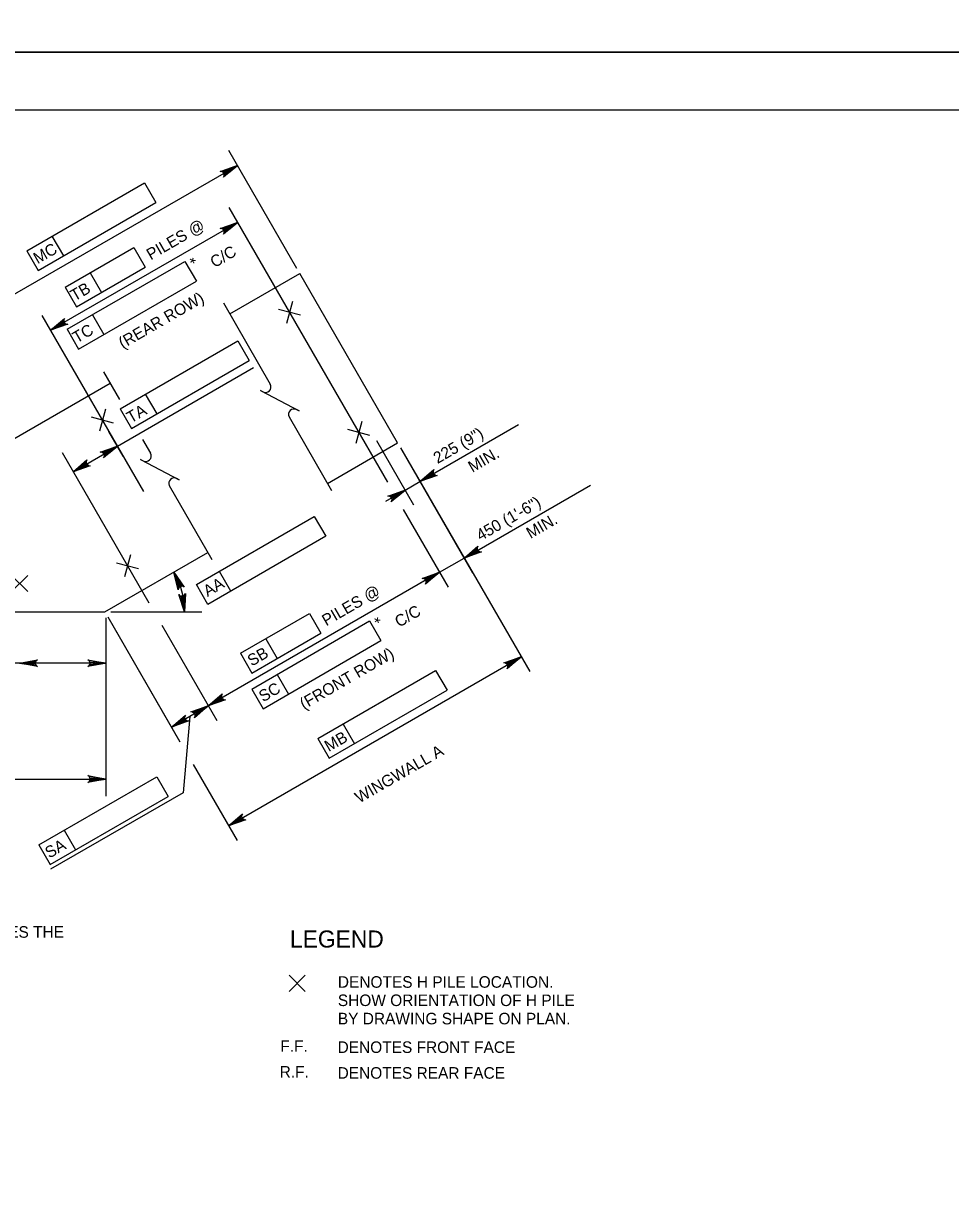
# Model space of a CAD drawing. Extents: x 638340 to 640241, y 295465 to 298435.
# Drawn here: x 639661.4 to 639902.2, y 295766.2 to 296067 of the extents above; entities that cross this region are included whole.
import ezdxf

# ---------------------------------------------------------------- set-up
doc = ezdxf.new("R2010")
doc.units = 0
for name, color, linetype in [('2', 7, 'Continuous'), ('3', 7, 'Continuous'), ('4', 7, 'Continuous'), ('PLT-BNDY', 7, 'Continuous')]:
    doc.layers.add(name, color=color, linetype=linetype)

# ---------------------------------------------------------------- blocks, each defined once
blk = doc.blocks.new('PILE')
at = {"layer": '2'}
for p, q in [((-2.651625, -2.651625), (2.651625, 2.651625)), ((-2.651625, 2.651625), (2.651625, -2.651625))]:
    blk.add_line(p, q, dxfattribs=at)

msp = doc.modelspace()

# ---------------------------------------------------------------- linework, layer by layer
at = {"layer": '2'}
for p, q in [((639316.46, 296044.46), (640102.46, 296044.46)), ((639732.41, 296003.31), (639714.76, 296033.89)), ((639642.12, 295986.84), (639716.97, 296030.05)), ((639662.28, 296007.88), (639692.86, 296025.53)), ((639692.86, 296025.53), (639695.81, 296020.41)), ((639665.24, 296002.76), (639695.81, 296020.41)), ((639714.78, 296019.09), (639755.91, 295947.84)), ((639716.99, 296015.26), (639668.49, 295987.25)), ((639668.83, 296011.66), (639671.79, 296006.54)), ((639662.28, 296007.88), (639665.24, 296002.76)), ((639672.23, 295998.41), (639690.11, 296008.73)), ((639690.11, 296008.73), (639693.07, 296003.61)), ((639672.79, 295987.49), (639703.37, 296005.13)), ((639703.37, 296005.13), (639706.32, 296000.02)), ((639675.19, 295993.29), (639693.07, 296003.61)), ((639678.78, 296002.19), (639681.73, 295997.07)), ((639672.23, 295998.41), (639675.19, 295993.29)), ((639675.74, 295982.38), (639706.32, 296000.02)), ((639692.67, 295945.37), (639666.27, 295991.09)), ((639679.34, 295991.27), (639682.29, 295986.16)), ((639672.79, 295987.49), (639675.74, 295982.38)), ((639686.52, 295966.88), (639717.1, 295984.52)), ((639717.1, 295984.52), (639720.05, 295979.4)), ((639685.85, 295957.18), (639721.13, 295977.54)), ((639689.47, 295961.76), (639720.05, 295979.4)), ((639693.07, 295970.66), (639696.02, 295965.54)), ((639686.52, 295966.88), (639689.47, 295961.76)), ((639764.35, 295947.99), (639789.98, 295962.79)), ((639687.35, 295954.58), (639683.64, 295961.01)), ((639674.32, 295950.52), (639685.85, 295957.18)), ((639753.09, 295958.63), (639762.73, 295941.94)), ((639759.33, 295956.69), (639766.57, 295944.15)), ((639759.33, 295956.69), (639778.04, 295924.28)), ((639759.33, 295956.69), (639792.85, 295898.63)), ((639671.45, 295955.5), (639693.97, 295916.48)), ((639760.51, 295945.77), (639764.35, 295947.99)), ((639775.83, 295928.11), (639808.67, 295947.08)), ((639760.51, 295945.77), (639755.4, 295942.82)), ((639706.37, 295921.21), (639736.93, 295938.89)), ((639736.93, 295938.89), (639739.89, 295933.78)), ((639760.01, 295940.74), (639771.65, 295920.59)), ((639739.89, 295933.78), (639709.33, 295916.1)), ((639769.43, 295924.42), (639775.83, 295928.11)), ((639769.43, 295924.42), (639709.4, 295889.76)), ((639715.25, 295919.53), (639712.3, 295924.64)), ((639709.33, 295916.1), (639706.37, 295921.21)), ((639766.88, 295922.95), (639764.32, 295921.47)), ((639684.13, 295914.16), (639707.7, 295914.16)), ((639682.78, 295912.62), (639682.78, 295866.33)), ((639683.36, 295912.83), (639702.07, 295880.42)), ((639683.36, 295912.83), (639701.95, 295880.63)), ((639717.79, 295903.39), (639735.65, 295913.74)), ((639720.73, 295894.1), (639751.28, 295911.79)), ((639735.65, 295913.74), (639738.62, 295908.63)), ((639751.28, 295911.79), (639754.25, 295906.68)), ((639697.33, 295910.68), (639711.61, 295885.93)), ((639720.75, 295898.28), (639738.62, 295908.63)), ((639723.69, 295888.99), (639754.25, 295906.68)), ((639724.33, 295907.18), (639727.3, 295902.07)), ((639714.66, 295858.61), (639790.63, 295902.47)), ((639717.79, 295903.39), (639720.75, 295898.28)), ((639682.78, 295900.81), (639619.52, 295900.81)), ((639737.86, 295881.25), (639768.43, 295898.91)), ((639768.43, 295898.91), (639771.39, 295893.79)), ((639727.28, 295897.89), (639730.24, 295892.78)), ((639720.73, 295894.1), (639723.69, 295888.99)), ((639740.81, 295876.14), (639771.39, 295893.79)), ((639709.4, 295889.76), (639699.86, 295884.25)), ((639704.67, 295887.03), (639702.86, 295867.18)), ((639744.41, 295885.04), (639747.36, 295879.92)), ((639737.86, 295881.25), (639740.81, 295876.14)), ((639705.49, 295874.49), (639716.88, 295854.77)), ((639523.08, 295870.76), (639682.78, 295870.76)), ((639665.46, 295853.68), (639696.04, 295871.31)), ((639696.04, 295871.31), (639698.99, 295866.2)), ((639668.41, 295848.56), (639698.99, 295866.2)), ((639702.86, 295867.18), (639668.49, 295847.34)), ((639672.01, 295857.46), (639674.96, 295852.34)), ((639665.46, 295853.68), (639668.41, 295848.56))]:
    msp.add_line(p, q, dxfattribs=at)
for points in [[(639716.97, 296030.05), (639713.37, 296026.97), (639713.56, 296027.36), (639713.56, 296027.72), (639713.45, 296028.02), (639713.25, 296028.27), (639712.93, 296028.44), (639712.5, 296028.48), (639716.97, 296030.05), (639712.93, 296028.44), (639713.25, 296028.27), (639716.97, 296030.05), (639713.45, 296028.02), (639713.56, 296027.72), (639716.97, 296030.05), (639713.56, 296027.36)], [(639716.99, 296015.26), (639713.39, 296012.17), (639713.58, 296012.56), (639713.58, 296012.93), (639713.47, 296013.23), (639713.27, 296013.47), (639712.95, 296013.65), (639712.52, 296013.68), (639716.99, 296015.26), (639712.95, 296013.65), (639713.27, 296013.47), (639716.99, 296015.26), (639713.47, 296013.23), (639713.58, 296012.93), (639716.99, 296015.26), (639713.58, 296012.56)], [(639668.49, 295987.25), (639672.09, 295990.34), (639671.9, 295989.95), (639671.89, 295989.58), (639672, 295989.28), (639672.21, 295989.04), (639672.52, 295988.86), (639672.96, 295988.83), (639668.49, 295987.25), (639672.52, 295988.86), (639672.21, 295989.04), (639668.49, 295987.25), (639672, 295989.28), (639671.89, 295989.58), (639668.49, 295987.25), (639671.9, 295989.95)], [(639685.85, 295957.18), (639682.25, 295954.09), (639682.44, 295954.49), (639682.44, 295954.85), (639682.33, 295955.15), (639682.13, 295955.39), (639681.81, 295955.57), (639681.38, 295955.6), (639685.85, 295957.18), (639681.81, 295955.57), (639682.13, 295955.39), (639685.85, 295957.18), (639682.33, 295955.15), (639682.44, 295954.85), (639685.85, 295957.18), (639682.44, 295954.49)], [(639674.32, 295950.52), (639677.92, 295953.61), (639677.73, 295953.21), (639677.73, 295952.85), (639677.84, 295952.55), (639678.04, 295952.31), (639678.36, 295952.13), (639678.79, 295952.09), (639674.32, 295950.52), (639678.36, 295952.13), (639678.04, 295952.31), (639674.32, 295950.52), (639677.84, 295952.55), (639677.73, 295952.85), (639674.32, 295950.52), (639677.73, 295953.21)], [(639764.35, 295947.99), (639767.95, 295951.07), (639767.76, 295950.68), (639767.76, 295950.32), (639767.87, 295950.02), (639768.07, 295949.77), (639768.39, 295949.6), (639768.82, 295949.56), (639764.35, 295947.99), (639768.39, 295949.6), (639768.07, 295949.77), (639764.35, 295947.99), (639767.87, 295950.02), (639767.76, 295950.32), (639764.35, 295947.99), (639767.76, 295950.68)], [(639760.51, 295945.77), (639756.91, 295942.68), (639757.1, 295943.08), (639757.11, 295943.44), (639757, 295943.74), (639756.79, 295943.98), (639756.48, 295944.16), (639756.04, 295944.2), (639760.51, 295945.77), (639756.48, 295944.16), (639756.79, 295943.98), (639760.51, 295945.77), (639757, 295943.74), (639757.11, 295943.44), (639760.51, 295945.77), (639757.1, 295943.08)], [(639775.83, 295928.11), (639779.42, 295931.2), (639779.24, 295930.8), (639779.23, 295930.44), (639779.34, 295930.14), (639779.55, 295929.9), (639779.86, 295929.72), (639780.3, 295929.69), (639775.83, 295928.11), (639779.86, 295929.72), (639779.55, 295929.9), (639775.83, 295928.11), (639779.34, 295930.14), (639779.23, 295930.44), (639775.83, 295928.11), (639779.24, 295930.8)], [(639700.51, 295924.48), (639703.19, 295920.57), (639702.81, 295920.79), (639702.46, 295920.84), (639702.15, 295920.76), (639701.88, 295920.59), (639701.67, 295920.29), (639701.59, 295919.86), (639700.51, 295924.48), (639701.67, 295920.29), (639701.88, 295920.59), (639700.51, 295924.48), (639702.15, 295920.76), (639702.46, 295920.84), (639700.51, 295924.48), (639702.81, 295920.79)], [(639769.43, 295924.42), (639765.83, 295921.33), (639766.02, 295921.73), (639766.02, 295922.09), (639765.91, 295922.39), (639765.71, 295922.63), (639765.39, 295922.81), (639764.96, 295922.85), (639769.43, 295924.42), (639765.39, 295922.81), (639765.71, 295922.63), (639769.43, 295924.42), (639765.91, 295922.39), (639766.02, 295922.09), (639769.43, 295924.42), (639766.02, 295921.73)], [(639703.27, 295914.17), (639701.73, 295918.65), (639702.03, 295918.34), (639702.37, 295918.2), (639702.68, 295918.19), (639702.99, 295918.29), (639703.27, 295918.52), (639703.46, 295918.91), (639703.27, 295914.17), (639703.27, 295918.52), (639702.99, 295918.29), (639703.27, 295914.17), (639702.68, 295918.19), (639702.37, 295918.2), (639703.27, 295914.17), (639702.03, 295918.34)], [(639790.63, 295902.47), (639787.03, 295899.38), (639787.22, 295899.78), (639787.22, 295900.14), (639787.11, 295900.44), (639786.91, 295900.68), (639786.59, 295900.86), (639786.16, 295900.9), (639790.63, 295902.47), (639786.59, 295900.86), (639786.91, 295900.68), (639790.63, 295902.47), (639787.11, 295900.44), (639787.22, 295900.14), (639790.63, 295902.47), (639787.22, 295899.78)], [(639660.44, 295900.81), (639665.1, 295901.68), (639664.75, 295901.44), (639664.56, 295901.12), (639664.51, 295900.81), (639664.56, 295900.5), (639664.75, 295900.19), (639665.1, 295899.94), (639660.44, 295900.81), (639664.75, 295900.19), (639664.56, 295900.5), (639660.44, 295900.81), (639664.51, 295900.81), (639664.56, 295901.12), (639660.44, 295900.81), (639664.75, 295901.44)], [(639682.78, 295900.81), (639678.12, 295899.94), (639678.48, 295900.19), (639678.67, 295900.5), (639678.72, 295900.81), (639678.67, 295901.12), (639678.48, 295901.44), (639678.12, 295901.68), (639682.78, 295900.81), (639678.48, 295901.44), (639678.67, 295901.12), (639682.78, 295900.81), (639678.72, 295900.81), (639678.67, 295900.5), (639682.78, 295900.81), (639678.48, 295900.19)], [(639709.4, 295889.76), (639713, 295892.85), (639712.81, 295892.46), (639712.81, 295892.09), (639712.92, 295891.79), (639713.12, 295891.55), (639713.44, 295891.37), (639713.87, 295891.34), (639709.4, 295889.76), (639713.44, 295891.37), (639713.12, 295891.55), (639709.4, 295889.76), (639712.92, 295891.79), (639712.81, 295892.09), (639709.4, 295889.76), (639712.81, 295892.46)], [(639699.86, 295884.25), (639703.46, 295887.34), (639703.27, 295886.94), (639703.26, 295886.58), (639703.37, 295886.28), (639703.58, 295886.04), (639703.89, 295885.86), (639704.33, 295885.83), (639699.86, 295884.25), (639703.89, 295885.86), (639703.58, 295886.04), (639699.86, 295884.25), (639703.37, 295886.28), (639703.26, 295886.58), (639699.86, 295884.25), (639703.27, 295886.94)], [(639709.4, 295889.76), (639705.8, 295886.68), (639705.99, 295887.07), (639705.99, 295887.43), (639705.88, 295887.73), (639705.68, 295887.98), (639705.36, 295888.15), (639704.93, 295888.19), (639709.4, 295889.76), (639705.36, 295888.15), (639705.68, 295887.98), (639709.4, 295889.76), (639705.88, 295887.73), (639705.99, 295887.43), (639709.4, 295889.76), (639705.99, 295887.07)], [(639682.78, 295870.76), (639678.12, 295869.89), (639678.48, 295870.14), (639678.67, 295870.45), (639678.72, 295870.76), (639678.67, 295871.08), (639678.48, 295871.39), (639678.12, 295871.64), (639682.78, 295870.76), (639678.48, 295871.39), (639678.67, 295871.08), (639682.78, 295870.76), (639678.72, 295870.76), (639678.67, 295870.45), (639682.78, 295870.76), (639678.48, 295870.14)], [(639714.66, 295858.61), (639718.26, 295861.69), (639718.08, 295861.3), (639718.07, 295860.94), (639718.18, 295860.64), (639718.38, 295860.39), (639718.7, 295860.22), (639719.14, 295860.18), (639714.66, 295858.61), (639718.7, 295860.22), (639718.38, 295860.39), (639714.66, 295858.61), (639718.18, 295860.64), (639718.07, 295860.94), (639714.66, 295858.61), (639718.08, 295861.3)]]:
    msp.add_lwpolyline(points, dxfattribs=at)
for points in [[(639714.17, 296029), (639714.66, 296028.15), (639716.97, 296030.05)], [(639714.19, 296014.2), (639714.68, 296013.35), (639716.99, 296015.26)], [(639670.8, 295989.16), (639671.29, 295988.3), (639668.49, 295987.25)], [(639683.05, 295956.13), (639683.54, 295955.27), (639685.85, 295957.18)], [(639676.63, 295952.42), (639677.13, 295951.57), (639674.32, 295950.52)], [(639766.66, 295949.89), (639767.15, 295949.04), (639764.35, 295947.99)], [(639757.71, 295944.72), (639758.2, 295943.87), (639760.51, 295945.77)], [(639778.14, 295930.02), (639778.63, 295929.16), (639775.83, 295928.11)], [(639766.63, 295923.37), (639767.12, 295922.52), (639769.43, 295924.42)], [(639766.63, 295923.37), (639767.12, 295922.52), (639769.43, 295924.42)], [(639787.83, 295901.42), (639788.32, 295900.56), (639790.63, 295902.47)], [(639663.4, 295901.3), (639663.4, 295900.32), (639660.44, 295900.81)], [(639679.64, 295901.3), (639679.64, 295900.32), (639682.59, 295900.81)], [(639711.71, 295891.67), (639712.2, 295890.81), (639709.4, 295889.76)], [(639706.6, 295888.71), (639707.09, 295887.86), (639709.4, 295889.76)], [(639702.17, 295886.15), (639702.66, 295885.3), (639699.86, 295884.25)], [(639679.83, 295871.25), (639679.83, 295870.27), (639682.78, 295870.76)], [(639716.98, 295860.51), (639717.47, 295859.66), (639714.66, 295858.61)]]:
    msp.add_lwpolyline(points, close=True, dxfattribs=at)
msp.add_arc((639682.59, 295914.16), 20.68, 359.9703, 29.9903, dxfattribs=at)
at = {"layer": '3'}
for p, q in [((639714.99, 295991.47), (639733.18, 296001.97)), ((639758.56, 295958.02), (639733.18, 296001.97)), ((639658.34, 295958.76), (639683.91, 295973.53)), ((639740.36, 295947.51), (639758.56, 295958.02)), ((639682.59, 295914.16), (639709.28, 295929.57)), ((639616.47, 295914.16), (639682.59, 295914.16))]:
    msp.add_line(p, q, dxfattribs=at)
at = {"layer": '4'}
for p, q in [((639713.33, 295994.33), (639725.52, 295973.22)), ((639682.23, 295976.43), (639686.35, 295969.3)), ((639730.38, 295964.81), (639741.43, 295945.66)), ((639692.36, 295958.89), (639694.42, 295955.32)), ((639699.27, 295946.91), (639710.33, 295927.76))]:
    msp.add_line(p, q, dxfattribs=at)
for points in [[(639723.58, 295971.28), (639722.96, 295971.61), (639733.01, 295966.3), (639732.33, 295966.66)], [(639692.47, 295953.38), (639691.85, 295953.72), (639701.9, 295948.41), (639701.23, 295948.76)]]:
    msp.add_lwpolyline(points, dxfattribs=at)
for centre, start, end in [((639724.29, 295972.51), 240, 30), ((639731.67, 295965.4), 62.1328, 204.6714), ((639693.19, 295954.61), 240, 30), ((639700.56, 295947.51), 62.1328, 204.6714)]:
    msp.add_arc(centre, 1.42, start, end, dxfattribs=at)
at = {"layer": 'PLT-BNDY'}
for points in [[(639276.46, 296653.46), (640117.46, 296653.46), (640117.46, 296059.46), (639276.46, 296059.46)], [(639276.46, 296059.46), (640117.46, 296059.46), (640117.46, 295465.46), (639276.46, 295465.46)]]:
    msp.add_lwpolyline(points, close=True, dxfattribs=at)

# ---------------------------------------------------------------- block references
at = {"layer": '2', "xscale": 0.78743606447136, "yscale": -0.7874360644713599, "rotation": -149.99999999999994}
for p in [(639730.48, 295991.89), (639681.98, 295963.89), (639748.48, 295960.72), (639688.44, 295926.06)]:
    msp.add_blockref('PILE', p, dxfattribs=at)
at = {"layer": '2', "xscale": 0.78743606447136, "yscale": 0.78743606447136}
for p in [(639660.45, 295921.54), (639732.46, 295817.73)]:
    msp.add_blockref('PILE', p, dxfattribs=at)

# ---------------------------------------------------------------- texts
at = {"layer": '2'}
for s, height, rotation, p in [('PILES @', 3, 30, (639694.48, 296005.36)), ('MC', 3, 29.9382, (639665.1, 296004.36)), ('C/C', 3, 29.9382, (639711.01, 296003.36)), ('*', 3, 59.9382, (639706.88, 296003.55)), ('TB', 3, 29.9382, (639674.72, 295994.7)), ('(REAR ROW)', 3, 30, (639687.22, 295982.37)), ('TC', 3, 29.9382, (639675.28, 295983.79)), ('TA', 3, 29.9382, (639689.31, 295963.04)), ('225 (9")', 3, 30, (639768.94, 295952.52)), ('MIN.', 3, 30, (639777.97, 295950.23)), ('450 (1\'-6")', 3.0001, 30, (639780.09, 295932.48)), ('MIN.', 3, 30, (639793.06, 295933.05)), ('AA', 3, 30.0491, (639709.22, 295917.98)), ('PILES @', 3, 30.0982, (639740.03, 295910.38)), ('C/C', 3, 30.0364, (639758.93, 295910.03)), ('*', 3, 60.0364, (639754.79, 295910.21)), ('SB', 3, 30.0364, (639720.7, 295899.93)), ('(FRONT ROW)', 3.0001, 30.0982, (639734.25, 295888.71)), ('SC', 3, 30.0364, (639723.64, 295890.64)), ('MB', 3, 29.9382, (639740.68, 295877.74)), ('WINGWALL A', 3, 30, (639748.6, 295864.39)), ('SA', 3, 29.9382, (639668.14, 295850.08))]:
    msp.add_text(s, height=height, rotation=rotation, dxfattribs=at).set_placement(p)
for s, p in [('THE DIAMETER FOR ROUND OR OCTAGONAL PILES AND TWO TIMES THE', (639528.2, 295829.57)), ('DENOTES H PILE LOCATION.', (639743.05, 295816.58)), ('SHOW ORIENTATION OF H PILE', (639743.05, 295811.83)), ('BY DRAWING SHAPE ON PLAN.', (639743.05, 295807.08))]:
    msp.add_text(s, height=3.0001, dxfattribs=at).set_placement(p)
at = {"layer": '4'}
for s, height, p in [('LEGEND', 4.429, (639730.62, 295827.02)), ('F.F.', 3, (639728.12, 295799.95)), ('DENOTES FRONT FACE', 3.0001, (639742.98, 295799.66)), ('R.F.', 3, (639727.94, 295793.26)), ('DENOTES REAR FACE', 3.0001, (639742.98, 295792.97))]:
    msp.add_text(s, height=height, dxfattribs=at).set_placement(p)

doc.saveas('drawing.dxf')
